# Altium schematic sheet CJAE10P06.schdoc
size 127 x 101 mm
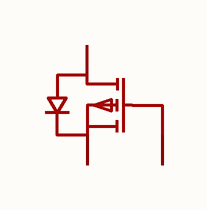
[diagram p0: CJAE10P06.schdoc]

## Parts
Q?  cjae10p06  [DFN-8_L3.0-W3.0-P0.65-BL_G48N03D3]  (value not drawn)

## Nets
NetQ?_1: Q?.1(S) Q?.2(S) Q?.3(S)
NetQ?_5: Q?.5(D) Q?.6(D) Q?.7(D) Q?.8(D)

Not connected (* = marked no-connect by the designer): Q? 4(G)

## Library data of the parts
Q? = cjae10p06: 数量:1个P沟道;漏源电压(Vdss):60V;连续漏极电流(Id):10A;导通电阻(RDS(on)):35mΩ@10V;耗散功率(Pd):3W;阈值电压(Vgs(th)):3V;; Manufacturer: CJ(江苏长电/长晶); AddInBom: yes; ModelId: 7d35045aab8a4197948fbab2a31c20b3; ModelTransform: 118.11,118.18874,0,0,0,0,0,0,0; Number: 1个P沟道; Drain to Source Voltage: 60V; Current - Continuous Drain(Id): 10A; Pd - Power Dissipation: 3W; Gate Threshold Voltage (Vgs(th)): 3V; Gate Charge(Qg): 52nC@10V; Input Capacitance(Ciss): 4.5nF; Reverse Transfer Capacitance (Crss@Vds): 515pF; Type: P沟道; Output Capacitance(Coss): 705pF; Vgs: ±20V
